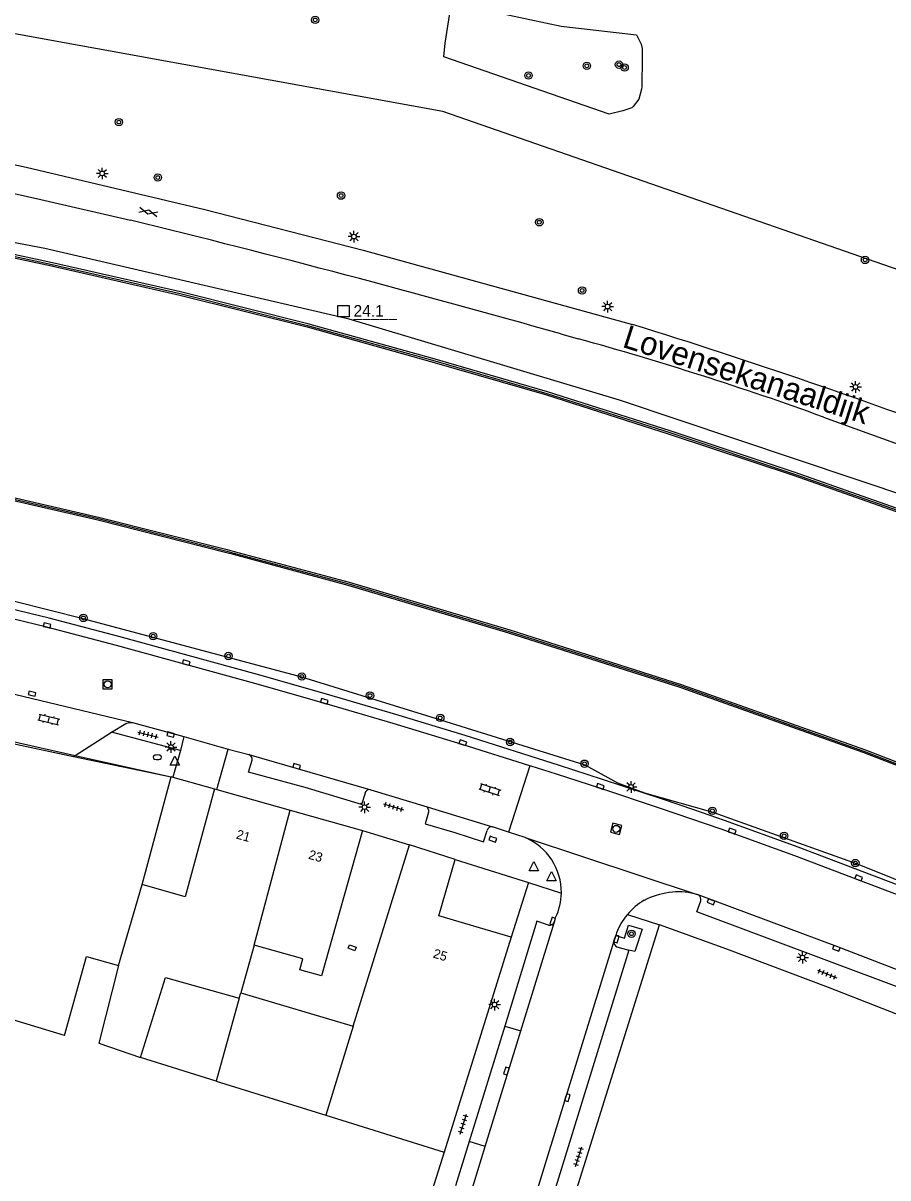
# Model space of a CAD drawing. Extents: x 132999 to 136000, y 398499 to 400501.
# Drawn here: x 134238.8 to 134331.8, y 398840.4 to 398964.6 of the extents above; entities that cross this region are included whole.
import ezdxf

# ---------------------------------------------------------------- set-up
doc = ezdxf.new("R2010")
doc.units = 0
for name, color, linetype in [('gg-afsc-hekwerk', 7, 'Continuous'), ('gg-afsc-muur', 7, 'Continuous'), ('gg-anno-huisnummerreeks BGT', 7, 'Continuous'), ('gg-anno-openbare ruimte label', 7, 'Continuous'), ('gg-bbg-gedigitaliseerde bebouwing', 7, 'Continuous'), ('gg-bbg-hoofdgebouw', 7, 'Continuous'), ('gg-bbg-tussenscheiding', 7, 'Continuous'), ('gg-knt-BGT kruinlijn', 7, 'Continuous'), ('gg-knt-verharding', 7, 'Continuous'), ('gg-knt-verharding nz', 7, 'Continuous'), ('gt-anno-nummer hm paal', 7, 'Continuous'), ('gt-grn-groengrens', 7, 'Continuous'), ('gt-grn-weggrens', 7, 'Continuous'), ('gt-symb-boom', 7, 'Continuous'), ('gt-symb-brandkraan', 7, 'Continuous'), ('gt-symb-gesloten verharding', 7, 'Continuous'), ('gt-symb-hm paal', 7, 'Continuous'), ('gt-symb-klinker verharding', 7, 'Continuous'), ('gt-symb-kolk', 7, 'Continuous'), ('gt-symb-kolk center center', 7, 'Continuous'), ('gt-symb-lichtmast', 7, 'Continuous'), ('gt-symb-rioolschacht', 7, 'Continuous'), ('gt-symb-tegel verharding', 7, 'Continuous'), ('gt-symb-waterafsluiter', 7, 'Continuous'), ('gx-grn-maaiveld', 7, 'Continuous')]:
    doc.layers.add(name, color=color, linetype=linetype)

# ---------------------------------------------------------------- blocks, each defined once
blk = doc.blocks.new('gt0-BOOM')
at = {"layer": 'gt-symb-boom'}
for radius in [0.4, 0.2]:
    blk.add_circle((0, 0), radius, dxfattribs=at)
blk = doc.blocks.new('gt0-GESVH1')
at = {"layer": 'gt-symb-gesloten verharding'}
for p, q in [((-0.99, -0.26), (0.01, 0.24)), ((0.01, -0.26), (-0.99, 0.24)), ((0.01, 0.24), (1.01, -0.26)), ((1.01, 0.24), (0.01, -0.26))]:
    blk.add_line(p, q, dxfattribs=at)
blk = doc.blocks.new('gt0-LMAST')
at = {"layer": 'gt-symb-lichtmast'}
for p, q in [((-0.18, 0.17), (-0.45, 0.44)), ((-0.01, 0.25), (-0.01, 0.62)), ((0.17, 0.17), (0.44, 0.44)), ((-0.26, 0), (-0.63, 0)), ((-0.18, -0.18), (-0.45, -0.45)), ((-0.01, -0.25), (-0.01, -0.63)), ((0.44, -0.45), (0.17, -0.18)), ((0.24, 0), (0.62, 0))]:
    blk.add_line(p, q, dxfattribs=at)
blk.add_circle((-0.01, 0), 0.25, dxfattribs=at)
blk = doc.blocks.new('gt0-KOLK')
at = {"layer": 'gt-symb-kolk'}
blk.add_lwpolyline([(0, 0), (0.37, 0), (0.37, 0.4), (-0.38, 0.4), (-0.38, 0), (0, 0)], dxfattribs=at)
blk = doc.blocks.new('gt0-TEG1')
at = {"layer": 'gt-symb-tegel verharding'}
for p, q in [((-1.12, 0), (1.12, 0)), ((-0.9, -0.25), (-0.9, 0.25)), ((-0.45, -0.25), (-0.45, 0.25)), ((0, -0.25), (0, 0.25)), ((0.45, -0.25), (0.45, 0.25)), ((0.9, -0.25), (0.9, 0.25))]:
    blk.add_line(p, q, dxfattribs=at)
blk = doc.blocks.new('gt0-BR')
at = {"layer": 'gt-symb-brandkraan'}
for centre, radius, start, end in [((-0.24, 0), 0.206, 107.5669, 252.4331), ((0.6, -2.66), 3, 106.892, 107.5669), ((0, -0.69), 0.938, 73.108, 106.892), ((-0.6, -2.66), 3, 72.4331, 73.108), ((0.24, 0), 0.206, 287.567, 72.4331), ((0.6, 2.66), 3, 252.4331, 253.108), ((0, 0.69), 0.938, 253.108, 286.8921), ((-0.6, 2.66), 3, 286.8921, 287.567)]:
    blk.add_arc(centre, radius, start, end, dxfattribs=at)
blk = doc.blocks.new('gt0-WAFSL')
at = {"layer": 'gt-symb-waterafsluiter'}
for p, q in [((-0.5, -0.33), (0, 0.67)), ((0, 0.67), (0.5, -0.33)), ((0.5, -0.33), (-0.5, -0.33))]:
    blk.add_line(p, q, dxfattribs=at)
blk = doc.blocks.new('gt0-KL1')
at = {"layer": 'gt-symb-klinker verharding'}
for p, q in [((-1.15, 0.3), (1.15, 0.3)), ((-1, -0.3), (-1, 0.3)), ((-0.5, 0.3), (-0.5, 0.45)), ((0, -0.3), (0, 0.3)), ((0.5, 0.3), (0.5, 0.45)), ((1, -0.3), (1, 0.3)), ((-1.15, -0.3), (1.15, -0.3)), ((-0.5, -0.45), (-0.5, -0.3)), ((0.5, -0.45), (0.5, -0.3))]:
    blk.add_line(p, q, dxfattribs=at)
blk = doc.blocks.new('gt0-RS')
at = {"layer": 'gt-symb-rioolschacht'}
blk.add_lwpolyline([(-0.5, -0.5), (0.5, -0.5), (0.5, 0.5), (-0.5, 0.5)], close=True, dxfattribs=at)
blk.add_circle((0, 0), 0.375, dxfattribs=at)
blk = doc.blocks.new('gt0-HMpaal')
at = {"layer": 'gt-symb-hm paal'}
blk.add_lwpolyline([(-0.6, 0.6), (0.6, 0.6), (0.6, -0.6), (-0.6, -0.6)], close=True, dxfattribs=at)
blk = doc.blocks.new('gt0-KOLKCC')
at = {"layer": 'gt-symb-kolk center center'}
blk.add_lwpolyline([(-0.38, 0.2), (0.38, 0.2), (0.38, -0.2), (-0.38, -0.2)], close=True, dxfattribs=at)

msp = doc.modelspace()

# ---------------------------------------------------------------- linework, layer by layer
at = {"layer": 'gg-afsc-hekwerk'}
for p, q in [((134237.42, 398887.37), (134244.42, 398885.81)), ((134244.42, 398885.81), (134254.73, 398883.52)), ((134298.01, 398838.05), (134307.24, 398867.6))]:
    msp.add_line(p, q, dxfattribs=at)
msp.add_lwpolyline([(134337.8, 398856.03), (134325.44, 398860.86), (134314.5, 398864.98), (134307.24, 398867.6)], dxfattribs=at)
at = {"layer": 'gg-afsc-muur'}
for p, q in [((134251.61, 398871.95), (134254.73, 398883.52)), ((134254.92, 398883.49), (134259.4, 398882.21)), ((134275.31, 398877.74), (134280.36, 398876.2))]:
    msp.add_line(p, q, dxfattribs=at)
for points in [[(134117.34, 398958.14), (134118.07, 398957.95), (134136.16, 398954.12), (134137.49, 398953.81), (134138.92, 398953.67), (134155.99, 398952.24), (134156.83, 398952.16), (134162.77, 398951.5), (134172.61, 398950.4), (134186.48, 398948.61), (134200.47, 398946.53), (134214.27, 398944.18), (134228.12, 398941.58), (134241.93, 398938.61), (134255.71, 398935.49), (134269.39, 398932.05), (134282.84, 398928.32), (134295.15, 398924.74), (134308.35, 398920.54), (134321.78, 398916.07), (134336.3, 398910.95)], [(134176.52, 398921.36), (134176.88, 398921.38), (134192.41, 398922.02), (134193.89, 398922.03), (134195.18, 398921.83), (134212.96, 398918.72), (134230.62, 398915.01), (134246.89, 398911.28), (134260.73, 398907.78), (134261.49, 398907.58), (134273.83, 398904.27), (134291.1, 398899.14), (134309.53, 398893.28), (134329.23, 398886.29), (134347.37, 398879.29), (134363.94, 398872.42), (134381.83, 398864.45), (134399.35, 398856.21), (134413.12, 398849.11), (134427.02, 398841.8), (134427.71, 398841.41), (134427.8, 398841.36)], [(134254.73, 398883.52), (134254.74, 398883.54), (134254.92, 398883.49)]]:
    msp.add_lwpolyline(points, dxfattribs=at)
at = {"layer": 'gg-bbg-gedigitaliseerde bebouwing'}
for p, q in [((134274.32, 398856.7), (134280.36, 398876.2)), ((134263.67, 398865.4), (134262.24, 398860.29)), ((134262.24, 398860.29), (134274.32, 398856.7)), ((134262.07, 398859.7), (134259.57, 398850.79)), ((134259.57, 398850.79), (134251.45, 398853.32))]:
    msp.add_line(p, q, dxfattribs=at)
for points in [[(134275.31, 398877.74), (134270.92, 398862.1), (134268.57, 398862.76), (134268.9, 398863.94), (134263.67, 398865.4)], [(134251.45, 398853.32), (134254.13, 398861.93), (134262.07, 398859.7)]]:
    msp.add_lwpolyline(points, dxfattribs=at)
at = {"layer": 'gg-bbg-hoofdgebouw'}
for p, q in [((134259.4, 398882.21), (134259.66, 398882.14)), ((134259.66, 398882.14), (134267.52, 398879.93)), ((134267.52, 398879.93), (134275.31, 398877.74)), ((134285.28, 398874.62), (134280.36, 398876.2)), ((134249.08, 398863.22), (134251.61, 398871.95)), ((134291.29, 398866.26), (134284.09, 398843.17)), ((134284.09, 398843.17), (134277.54, 398822.16))]:
    msp.add_line(p, q, dxfattribs=at)
for points in [[(134243.26, 398855.71), (134217.59, 398863.48), (134214.39, 398853.15), (134207.38, 398855.36), (134212.88, 398892.2)], [(134259.4, 398882.21), (134256.26, 398870.61), (134251.61, 398871.95)], [(134291.29, 398866.26), (134283.54, 398868.58), (134285.28, 398874.62)], [(134243.26, 398855.71), (134245.64, 398864.18), (134249.08, 398863.22)]]:
    msp.add_lwpolyline(points, dxfattribs=at)
at = {"layer": 'gg-bbg-tussenscheiding'}
for p, q in [((134263.67, 398865.4), (134267.52, 398879.93)), ((134262.07, 398859.7), (134262.24, 398860.29)), ((134274.32, 398856.7), (134271.37, 398847.14)), ((134259.57, 398850.79), (134271.37, 398847.14)), ((134271.37, 398847.14), (134284.09, 398843.17))]:
    msp.add_line(p, q, dxfattribs=at)
msp.add_lwpolyline([(134249.08, 398863.22), (134246.95, 398854.87), (134251.45, 398853.32)], dxfattribs=at)
at = {"layer": 'gg-knt-BGT kruinlijn'}
for p, q in [((134241.17, 398940.32), (134190.26, 398950)), ((134273.9, 398932.72), (134241.17, 398940.32)), ((134302.95, 398924), (134273.9, 398932.72)), ((134336.58, 398912.73), (134302.95, 398924))]:
    msp.add_line(p, q, dxfattribs=at)
at = {"layer": 'gg-knt-verharding'}
for p, q in [((134296.66, 398931.13), (134298.5, 398930.62)), ((134324.89, 398922.19), (134351.85, 398912.42)), ((134250.6, 398889.36), (134256.12, 398887.86)), ((134244.42, 398885.81), (134248.33, 398888.3)), ((134255.73, 398886.34), (134248.33, 398888.3)), ((134256.12, 398887.86), (134255.73, 398886.34)), ((134237.52, 398887.12), (134244.25, 398885.71)), ((134255.73, 398886.34), (134254.92, 398883.49)), ((134259.66, 398882.14), (134260.86, 398886.5)), ((134260.86, 398886.5), (134263.1, 398885.9)), ((134244.25, 398885.71), (134244.42, 398885.81)), ((134244.25, 398885.71), (134254.73, 398883.52)), ((134276.2, 398882.13), (134282.26, 398880.27)), ((134291.02, 398877.56), (134289.3, 398878.13)), ((134292.8, 398876.98), (134291.02, 398877.56)), ((134285.28, 398874.62), (134293.18, 398872.16)), ((134293.18, 398872.16), (134291.29, 398866.26)), ((134308.65, 398871.11), (134308.28, 398871.07)), ((134311.43, 398870.81), (134311.32, 398870.85)), ((134295.95, 398867.92), (134296.08, 398868.37)), ((134303.81, 398868.71), (134303.58, 398868.42)), ((134302.36, 398865.86), (134302.55, 398866.47)), ((134302.68, 398865.24), (134303.94, 398864.86)), ((134290.61, 398856.72), (134286.79, 398844.3)), ((134286.79, 398844.3), (134285.32, 398839.54))]:
    msp.add_line(p, q, dxfattribs=at)
for points in [[(134232.71, 398950.48), (134239.14, 398949.06), (134258.37, 398944.51), (134275.38, 398940.13), (134304.34, 398932.16)], [(134232.07, 398947.54), (134240.73, 398945.6), (134250.36, 398943.36)], [(134293.32, 398884.71), (134286.05, 398886.98), (134278.61, 398889.24), (134271.15, 398891.43), (134263.74, 398893.54), (134248.85, 398897.64), (134241.36, 398899.59), (134233.82, 398901.42), (134226.24, 398903.08), (134218.64, 398904.52), (134211, 398905.78), (134203.35, 398906.87), (134195.68, 398907.83), (134187.99, 398908.71), (134180.29, 398909.5), (134172.6, 398910.21), (134164.9, 398910.85), (134156.52, 398911.49)], [(134248.33, 398888.3), (134249.86, 398889.24), (134250.22, 398889.36), (134250.6, 398889.36)], [(134275.59, 398881.77), (134275.2, 398880.54), (134269.14, 398882.35), (134263.05, 398884.02), (134263.44, 398885.31)], [(134296.18, 398883.79), (134293.45, 398884.67), (134293.32, 398884.71)], [(134310.64, 398879), (134307.38, 398880.12), (134300.83, 398882.28), (134296.18, 398883.79)], [(134282.26, 398880.27), (134282.4, 398879.94), (134282.4, 398879.7), (134282.05, 398878.47), (134285.24, 398877.51), (134288.34, 398876.52), (134288.73, 398877.75)], [(134427.21, 398826.04), (134418.12, 398831.11), (134411.3, 398834.81), (134404.46, 398838.45), (134397.58, 398842.02), (134391.56, 398845.06), (134385.51, 398848.02), (134378.52, 398851.32), (134364.44, 398857.75), (134357.34, 398860.88), (134350.22, 398863.9), (134343.06, 398866.84), (134335.85, 398869.68), (134321.82, 398875.01), (134313.9, 398877.88), (134310.64, 398879)], [(134338.56, 398860.02), (134338.03, 398858.78), (134332.8, 398860.93), (134311.27, 398868.98), (134311.69, 398870.19)], [(134295.33, 398867.58), (134294.08, 398867.99), (134290.61, 398856.72)], [(134302.55, 398866.47), (134303.49, 398866.17), (134303.93, 398867.58), (134305.38, 398867.15), (134304.61, 398864.72), (134303.94, 398864.86)], [(134303.94, 398864.86), (134286.58, 398808.54), (134285.3, 398808.95)]]:
    msp.add_lwpolyline(points, dxfattribs=at)
for centre, radius, start, end in [((133947.44, 397702.92), 1276.89, 74.12814, 76.27693), ((134098.22, 398269.05), 694.41, 69.41988, 72.7326), ((134203.36, 398587.08), 356.47, 70.0657, 74.5201), ((134262.95, 398885.42), 0.505, 347.0608, 72.719), ((134276.07, 398881.64), 0.505, 75.9569, 164.2395), ((134289.2, 398877.66), 0.472, 77.6705, 169.616), ((134290.34, 398871.11), 6.36, 359.1612, 67.2595), ((134290.35, 398871.11), 6.35, 334.5045, 359.1932), ((134308.93, 398864.46), 6.66, 119.8853, 140.2676), ((134309.42, 398862.78), 8.37, 97.8807, 117.1087), ((134309.36, 398864.64), 6.51, 72.5344, 96.2192), ((134311.19, 398870.35), 0.521, 342.7843, 62.0977), ((134295.46, 398868.08), 0.519, 255.6216, 341.8442), ((134308.2, 398864.75), 5.9, 141.5595, 163.0519), ((134302.85, 398865.72), 0.508, 164.4006, 250.8636)]:
    msp.add_arc(centre, radius, start, end, dxfattribs=at)
at = {"layer": 'gg-knt-verharding nz'}
for p, q in [((134235, 398893.1), (134250.6, 398889.36)), ((134256.12, 398887.86), (134260.86, 398886.5)), ((134263.1, 398885.9), (134276.2, 398882.13)), ((134282.26, 398880.27), (134289.3, 398878.13)), ((134292.34, 398856.19), (134295.95, 398867.92)), ((134302.36, 398865.86), (134284.73, 398808.69)), ((134290.61, 398856.72), (134292.34, 398856.19)), ((134288.51, 398843.77), (134292.34, 398856.19)), ((134288.51, 398843.77), (134286.79, 398844.3)), ((134286.92, 398838.6), (134288.51, 398843.77))]:
    msp.add_line(p, q, dxfattribs=at)
msp.add_lwpolyline([(134339.22, 398860.28), (134326.34, 398865.26), (134311.43, 398870.81)], dxfattribs=at)
at = {"layer": 'gt-grn-groengrens'}
for points in [[(134356.34, 398929.9), (134283.95, 398955.04), (134172.12, 398975.37), (134133.33, 398982.45), (134117.1, 398985.27)], [(134284.08, 398960.94), (134284.22, 398962.39), (134284.88, 398966.74), (134296.69, 398964.22), (134304.78, 398963.31), (134305.28, 398962.29), (134305.38, 398961.83), (134305.4, 398960.82), (134305.34, 398957.74), (134305.31, 398957.44), (134305.03, 398956.39), (134304.44, 398955.58), (134304.27, 398955.46), (134303.32, 398955.12), (134301.85, 398954.75), (134284.08, 398960.94)], [(134296.49, 398884.74), (134286.35, 398887.94), (134278.9, 398890.2), (134271.43, 398892.39), (134264.01, 398894.51), (134249.11, 398898.61), (134241.61, 398900.56), (134234.04, 398902.39), (134226.44, 398904.06), (134218.81, 398905.51), (134211.15, 398906.77), (134203.49, 398907.86), (134195.8, 398908.82), (134188.1, 398909.7), (134180.38, 398910.49), (134172.68, 398911.2), (134164.98, 398911.85), (134156.6, 398912.48)], [(134310.96, 398879.95), (134307.7, 398881.07), (134301.14, 398883.23), (134296.49, 398884.74)], [(134427.78, 398826.87), (134418.6, 398831.98), (134411.78, 398835.69), (134404.93, 398839.33), (134398.04, 398842.91), (134392.01, 398845.96), (134385.94, 398848.93), (134378.94, 398852.23), (134364.85, 398858.66), (134357.74, 398861.8), (134350.6, 398864.83), (134343.43, 398867.76), (134336.21, 398870.61), (134322.17, 398875.95), (134314.23, 398878.82), (134310.96, 398879.95)]]:
    msp.add_lwpolyline(points, dxfattribs=at)
at = {"layer": 'gt-grn-weggrens'}
for p, q in [((134293.32, 398884.71), (134291.02, 398877.56)), ((134292.8, 398876.98), (134311.32, 398870.85)), ((134293.18, 398872.16), (134296.7, 398871.02)), ((134303.81, 398868.71), (134307.24, 398867.6))]:
    msp.add_line(p, q, dxfattribs=at)
at = {"layer": 'gx-grn-maaiveld'}
for points in [[(134336.36, 398911.11), (134321.83, 398916.24), (134308.41, 398920.71), (134295.2, 398924.91), (134282.89, 398928.49), (134269.43, 398932.22), (134255.75, 398935.66), (134241.97, 398938.79), (134228.15, 398941.75), (134214.3, 398944.36), (134200.5, 398946.7), (134186.5, 398948.78), (134172.63, 398950.57), (134162.79, 398951.67), (134156.85, 398952.34), (134156.01, 398952.42), (134138.94, 398953.84), (134137.52, 398953.99), (134136.2, 398954.29), (134132.62, 398955.05)], [(134138.9, 398953.49), (134155.98, 398952.07), (134156.82, 398951.99), (134162.76, 398951.33), (134172.59, 398950.23), (134186.46, 398948.43), (134200.45, 398946.35), (134214.24, 398944.01), (134228.08, 398941.41), (134241.89, 398938.44), (134255.67, 398935.32), (134269.35, 398931.88), (134282.79, 398928.15), (134295.1, 398924.57), (134308.3, 398920.37), (134321.72, 398915.91), (134336.24, 398910.78)], [(134427.77, 398841.18), (134427.63, 398841.26), (134426.94, 398841.64), (134413.04, 398848.95), (134399.27, 398856.05), (134381.75, 398864.3), (134363.87, 398872.26), (134347.3, 398879.13), (134329.17, 398886.13), (134309.48, 398893.12), (134291.05, 398898.97), (134273.79, 398904.1), (134261.44, 398907.41), (134260.68, 398907.61), (134246.85, 398911.11), (134230.59, 398914.84), (134212.93, 398918.55), (134195.15, 398921.66), (134193.88, 398921.86), (134192.41, 398921.84), (134176.89, 398921.2), (134176.52, 398921.19), (134176.52, 398921.14)], [(134343.54, 398868.11), (134328.55, 398874.11), (134313.01, 398879.69), (134305.66, 398881.77), (134302.76, 398882.85), (134299.27, 398884.77), (134283.74, 398889.61), (134268.8, 398894.22), (134245.27, 398900.49), (134230.48, 398904.22), (134214.84, 398907.14), (134206.05, 398908.51), (134190.93, 398910.19), (134175.23, 398911.68), (134159.21, 398912.99), (134143.34, 398914.15), (134127.06, 398914.87), (134110.94, 398914.88), (134094.35, 398915.09), (134078.37, 398914.57), (134062.62, 398913.97), (134051.49, 398913.54)], [(134230.66, 398915.18), (134246.93, 398911.45), (134260.77, 398907.95), (134261.53, 398907.74), (134273.88, 398904.44), (134291.15, 398899.31), (134309.59, 398893.45), (134329.29, 398886.46), (134347.43, 398879.46)]]:
    msp.add_lwpolyline(points, dxfattribs=at)

# ---------------------------------------------------------------- block references
at = {"layer": 'gt-symb-boom'}
for p in [(134270.23, 398964.9), (134299.44, 398959.96), (134302.9, 398960.09), (134303.5, 398959.78), (134293.17, 398958.92), (134249.12, 398953.91), (134253.3, 398947.95), (134273.01, 398946.01), (134294.33, 398943.14), (134329.36, 398939.09), (134298.93, 398935.81), (134245.3, 398900.6), (134252.81, 398898.64), (134260.9, 398896.5), (134268.8, 398894.3), (134276.12, 398892.25), (134283.68, 398889.85), (134291.19, 398887.26), (134299.19, 398884.92), (134312.94, 398879.86), (134320.65, 398877.17), (134328.31, 398874.24), (134304.25, 398866.64)]:
    msp.add_blockref('gt0-BOOM', p, dxfattribs=at)
at = {"layer": 'gt-symb-brandkraan'}
msp.add_blockref('gt0-BR', (134253.26, 398885.62), dxfattribs=at)
at = {"layer": 'gt-symb-gesloten verharding', "rotation": -14.008443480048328}
msp.add_blockref('gt0-GESVH1', (134252.27, 398944.25), dxfattribs=at)
at = {"layer": 'gt-symb-hm paal'}
msp.add_blockref('gt0-HMpaal', (134273.27, 398933.59), dxfattribs=at)
at = {"layer": 'gt-symb-klinker verharding'}
for p, rotation in [((134241.58, 398889.68), -13.466776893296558), ((134289, 398882.14), -18.00007459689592)]:
    msp.add_blockref('gt0-KL1', p, dxfattribs=dict(at, rotation=rotation))
at = {"layer": 'gt-symb-kolk'}
for p, rotation in [((134241.36, 398899.59), -14.008443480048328), ((134256.31, 398895.6), -15.315451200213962), ((134239.75, 398892.26), -13.59156043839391), ((134271.15, 398891.43), -16.13420459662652), ((134254.74, 398888.25), 165.04643525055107), ((134286.05, 398886.98), -17.149043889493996), ((134268.2, 398884.45), -16.02410965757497), ((134300.83, 398882.28), -18.181268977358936), ((134315.01, 398877.49), -19.50357323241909), ((134289.39, 398877), 161.45633066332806), ((134328.61, 398872.45), -20.790725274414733), ((134312.86, 398870.27), 159.33669709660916), ((134295.96, 398867.93), 71.58316555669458), ((134302.44, 398866.12), -106.98473253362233), ((134326.34, 398865.26), 159.20927472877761), ((134290.99, 398851.82), 72.83405394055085), ((134297.16, 398849.06), -107.27542027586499)]:
    msp.add_blockref('gt0-KOLK', p, dxfattribs=dict(at, rotation=rotation))
at = {"layer": 'gt-symb-kolk center center', "rotation": -20.247501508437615}
msp.add_blockref('gt0-KOLKCC', (134274.21, 398865.14), dxfattribs=at)
at = {"layer": 'gt-symb-lichtmast'}
for p in [(134247.33, 398948.39), (134274.4, 398941.6), (134301.68, 398934.08), (134328.34, 398925.43), (134254.73, 398886.72), (134304.2, 398882.43), (134275.54, 398880.25), (134322.64, 398864.09), (134289.52, 398859.03)]:
    msp.add_blockref('gt0-LMAST', p, dxfattribs=at)
at = {"layer": 'gt-symb-rioolschacht'}
msp.add_blockref('gt0-RS', (134247.9, 398893.46), dxfattribs=at)
at = {"layer": 'gt-symb-rioolschacht', "rotation": 164.5740296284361}
msp.add_blockref('gt0-RS', (134302.6, 398877.92), dxfattribs=at)
at = {"layer": 'gt-symb-tegel verharding'}
for p, rotation in [((134252.25, 398888.06), -14.008443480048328), ((134278.65, 398880.28), -16.984732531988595), ((134325.27, 398862.31), -22.024845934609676), ((134286.16, 398846.17), 72.6698913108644), ((134298.56, 398842.67), 72.6698913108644)]:
    msp.add_blockref('gt0-TEG1', p, dxfattribs=dict(at, rotation=rotation))
at = {"layer": 'gt-symb-waterafsluiter'}
for p in [(134255.15, 398885.08), (134293.75, 398873.73), (134295.64, 398872.67)]:
    msp.add_blockref('gt0-WAFSL', p, dxfattribs=at)

# ---------------------------------------------------------------- texts
at = {"layer": 'gg-anno-huisnummerreeks BGT'}
for s, rotation, p in [('21', 344.3, (134261.66, 398876.9)), ('23', 344.3, (134269.43, 398874.72)), ('25', 343.3, (134282.83, 398864.1))]:
    msp.add_text(s, height=1, rotation=rotation, dxfattribs=at).set_placement(p)
at = {"layer": 'gg-anno-openbare ruimte label'}
msp.add_text('Lovensekanaaldijk', height=2.5, rotation=342.3, dxfattribs=at).set_placement((134303.15, 398929.76))
at = {"layer": 'gt-anno-nummer hm paal'}
msp.add_text('24.1', height=1.25, dxfattribs=at).set_placement((134274.35, 398932.99))
at = {"layer": 'gt-symb-hm paal'}
msp.add_text('_____', height=1.25, dxfattribs=at).set_placement((134274.35, 398932.99))

doc.saveas('drawing.dxf')
